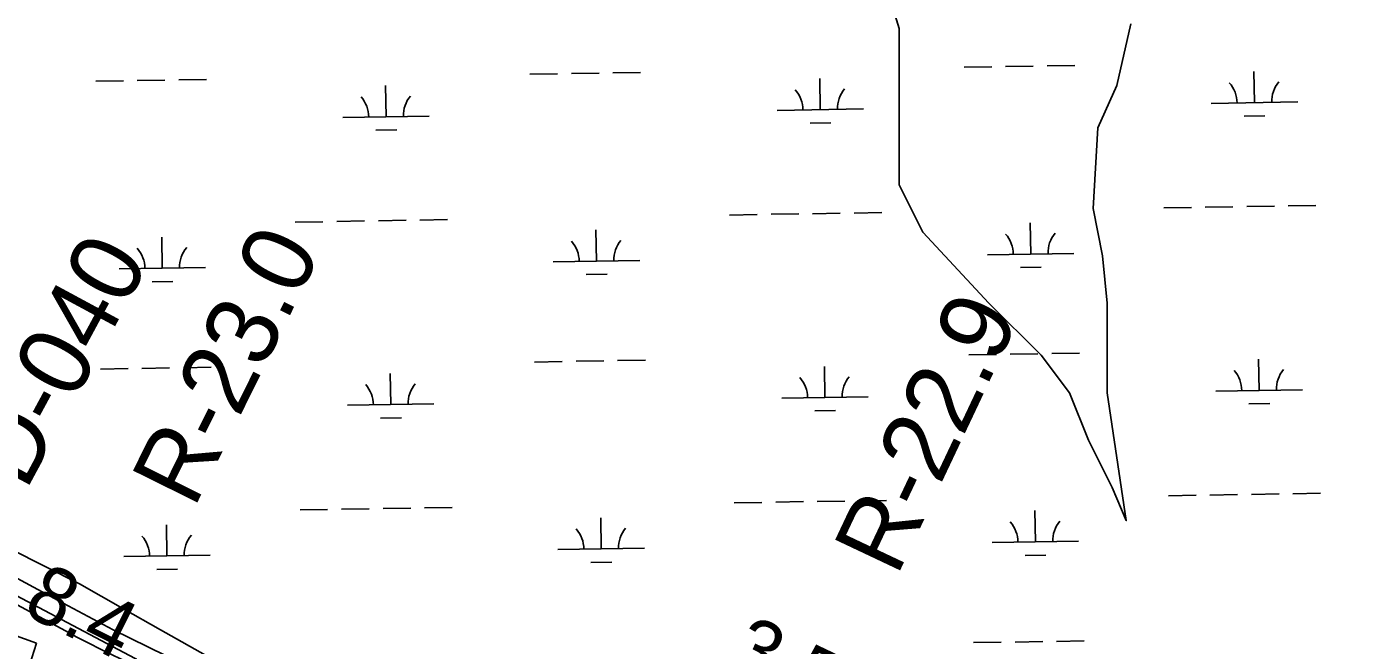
# Model space of a CAD drawing. Extents: x 3855477 to 3893699, y 299188 to 325115.
# Drawn here: x 3865905 to 3867459, y 315024 to 315738 of the extents above; entities that cross this region are included whole.
import ezdxf

# ---------------------------------------------------------------- set-up
doc = ezdxf.new("R2010")
doc.units = 0
for name, color, linetype in [('V-LEVE-TOET', 7, 'Continuous'), ('V-RIVR-EDGE', 7, 'Continuous'), ('V-RIVR-RANG', 7, 'Continuous'), ('V-RIVR-RANG-IDEN', 7, 'Continuous'), ('V-RRAP-FSHR', 7, 'Continuous'), ('V-RRAP-RVMT', 7, 'Continuous'), ('V-TOPO-MINR', 7, 'Continuous'), ('V-TOPO-SHOR', 7, 'Continuous'), ('V-WETL-SWMP', 7, 'Continuous')]:
    doc.layers.add(name, color=color, linetype=linetype)

msp = doc.modelspace()

# ---------------------------------------------------------------- linework, layer by layer
at = {"layer": 'V-LEVE-TOET'}
for points in [[(3866235.4, 314911.4), (3866259.2, 314902.4), (3866270.4, 314903.5), (3866272.4, 314911.4), (3866266.9, 314917.9), (3866245.6, 314933.2), (3866221.5, 314948.2), (3866197.3, 314962), (3866174.4, 314975.4), (3866153, 314987.1), (3866118.2, 315008.6), (3866060, 315041.4), (3866016.5, 315066.2), (3865966.2, 315094.5), (3865886.2, 315135.2)], [(3865851.4, 315124), (3865941.7, 315075.3), (3866005.1, 315041.6), (3866086.3, 315001.7), (3866168.6, 314955.9), (3866221.2, 314920.7), (3866235.4, 314911.4)]]:
    msp.add_lwpolyline(points, dxfattribs=at)
at = {"layer": 'V-RIVR-EDGE'}
msp.add_spline([(3862579.1, 316706.6), (3862618.9, 316682.6), (3862652.8, 316666.1), (3862683, 316656.5), (3862696.2, 316652.9), (3862701.3, 316646.9), (3862715.3, 316640.1), (3862730, 316634.5), (3862738.8, 316633.6), (3862748.3, 316626.1), (3862763.5, 316620.4), (3862771, 316614.8), (3862792.5, 316606), (3862806.8, 316598.8), (3862818, 316594.4), (3862834.3, 316586.8), (3862853, 316578.4), (3862861.8, 316570.8), (3862880.1, 316564.8), (3862890, 316564.7), (3862900, 316564.3), (3862907.6, 316561.5), (3862923.9, 316554.7), (3862944.6, 316544.7), (3862975.6, 316529), (3863008.7, 316511), (3863036.9, 316493.4), (3863051.3, 316484.2), (3863059.6, 316479.8), (3863073.1, 316469.4), (3863078.7, 316461.8), (3863091, 316455.4), (3863113.7, 316446.6), (3863137.2, 316440.6), (3863166.3, 316430.5), (3863183.4, 316425.7), (3863207.7, 316412.1), (3863228, 316399.7), (3863238.3, 316395.7), (3863252.7, 316390.5), (3863259.4, 316385.3), (3863266.6, 316378.1), (3863269.4, 316370.9), (3863279.3, 316363.3), (3863294.4, 316355.7), (3863309.2, 316346.9), (3863343, 316331.3), (3863355.3, 316322.1), (3863380.4, 316304.5), (3863423.4, 316277.3), (3863452, 316258.5), (3863472.7, 316247.6), (3863532.4, 316214.8), (3863576.2, 316192.8), (3863612, 316174), (3863663, 316147.9), (3863702, 316129.9), (3863762.1, 316101.5), (3863803.5, 316080.6), (3863847.7, 316056.6), (3863876.3, 316044.2), (3863896.6, 316031.8), (3863917.7, 316020.6), (3863971.8, 315991.3), (3864020.8, 315966.1), (3864054.2, 315946.5), (3864091.6, 315926.9), (3864114.7, 315913.7), (3864131.9, 315906.9), (3864147, 315897.7), (3864174, 315883.6), (3864183.2, 315874.1), (3864194.3, 315870.4), (3864207.5, 315866.8), (3864224.2, 315858.8), (3864239.3, 315850.4), (3864262.4, 315840), (3864273.6, 315837.2), (3864288.7, 315830.4), (3864303.8, 315827.9), (3864315.4, 315825.1), (3864338.5, 315817.1), (3864360.8, 315810.6), (3864391.4, 315792.2), (3864418.9, 315776.2), (3864436, 315762.2), (3864459, 315741.9), (3864510.4, 315709.8), (3864535.4, 315695.8), (3864549, 315685.4), (3864561.3, 315675.8), (3864568.8, 315666.7), (3864582.4, 315656.7), (3864595.1, 315647.1), (3864600.7, 315641.1), (3864607, 315633.1), (3864612.6, 315626.3), (3864620.2, 315622.7), (3864637.3, 315615.9), (3864659.6, 315609), (3864678.3, 315601), (3864697.4, 315595.4), (3864745.6, 315571.8), (3864769.9, 315563.7), (3864787.4, 315555.7), (3864811.2, 315540.5), (3864821.2, 315537.7), (3864833.2, 315537.7), (3864842.3, 315536.5), (3864849.5, 315531.3), (3864857.4, 315522.9), (3864872.2, 315516.9), (3864908, 315506), (3864925.1, 315500.4), (3864937.9, 315498.8), (3864948.6, 315491.6), (3864957, 315489.5), (3864964.2, 315487.5), (3865017.5, 315468.3), (3865068.5, 315449.8), (3865096.3, 315439.4), (3865128.6, 315425), (3865154.9, 315414.9), (3865176, 315401.7), (3865212.2, 315385.7), (3865243.6, 315368.5), (3865263.1, 315356.5), (3865277.9, 315348.1), (3865297, 315338.1), (3865316.5, 315331.2), (3865337.2, 315318), (3865369.4, 315298.4), (3865405.2, 315275.2), (3865431.9, 315259.6), (3865448.2, 315254), (3865473.7, 315238.4), (3865499.1, 315224.8), (3865515.1, 315218), (3865531.8, 315209.2), (3865549.7, 315199.5), (3865571.2, 315191.5), (3865609, 315173.1), (3865654, 315145.5), (3865693.8, 315123.1), (3865732.8, 315101.8), (3865776.9, 315077.4), (3865798.4, 315063.8), (3865826.7, 315046.6), (3865853.4, 315032.6), (3865883.2, 315017.4), (3865895.1, 315011.4), (3865904.3, 315003.8), (3865913, 314994.6), (3865919.8, 314990.2), (3865927.8, 314987.4), (3865939.7, 314983.4), (3865950.5, 314980.6), (3865961.6, 314976.5), (3865977.5, 314967.3), (3866028.9, 314942.9), (3866056.7, 314928.5), (3866076.6, 314915.3), (3866096.5, 314901.7), (3866120.4, 314888.5), (3866143.9, 314878.1), (3866161.4, 314867.2), (3866178.1, 314862.8), (3866201.2, 314856.8), (3866223.1, 314850.4), (3866245.8, 314837.5), (3866263.7, 314827.1), (3866282.8, 314818.7), (3866292.4, 314818.7), (3866300.8, 314818.3), (3866309.9, 314816.3), (3866326.7, 314808.7), (3866348.5, 314791.1), (3866360.1, 314786.3), (3866377.6, 314778.6), (3866387.5, 314775), (3866394.3, 314767.4), (3866401.9, 314762.2), (3866413.8, 314757), (3866423.4, 314751.4), (3866432.1, 314749.8), (3866437.7, 314746.2), (3866445.6, 314739.4), (3866454.4, 314732.2), (3866485.5, 314719), (3866510.5, 314708.6), (3866533.2, 314691.4), (3866542, 314691.3), (3866549.9, 314690.9), (3866556.3, 314686.5), (3866561.9, 314678.5), (3866573.8, 314670.1), (3866598.9, 314663.7), (3866631.1, 314649.3), (3866660.6, 314640.4), (3866694.9, 314628.4), (3866748.2, 314604.4), (3866780.4, 314591.5), (3866811.1, 314575.5), (3866846.9, 314561.5), (3866895.5, 314539), (3866932.1, 314524.6), (3866954.8, 314513.4), (3866988.3, 314500.5), (3867018.5, 314486.5), (3867041.2, 314475.3), (3867068.7, 314458.5), (3867097.3, 314440.1), (3867124, 314432.5), (3867147.1, 314433.2), (3867169.4, 314428), (3867197.3, 314417.1), (3867215.2, 314410.7), (3867238.7, 314401.5), (3867251.4, 314396.3), (3867258.6, 314395.9), (3867271.4, 314397.4), (3867288.1, 314397.8), (3867302.4, 314396.1), (3867345.5, 314385.3), (3867427.5, 314359.6), (3867438.3, 314357.9), (3867445, 314357.9), (3867453.4, 314369.5), (3867458.2, 314381.4), (3867462.3, 314395.8), (3867462.3, 314404.1), (3867460.7, 314411.7), (3867457.1, 314414.1), (3867450.8, 314416.1), (3867442.8, 314416.5), (3867438.8, 314420.1), (3867443.2, 314422.1), (3867451.6, 314428.1), (3867458.8, 314437.2), (3867459.6, 314442.8), (3867460, 314450.8), (3867463.6, 314455.1), (3867470.8, 314463.9), (3867472, 314469.5), (3867472.4, 314477), (3867471.6, 314485), (3867465.7, 314504.5), (3867463.7, 314514.5), (3867463.4, 314524.5), (3867464.2, 314541.2), (3867469.1, 314571.1), (3867474.7, 314579.8), (3867478.3, 314581.4), (3867485, 314582.6), (3867525.3, 314574.9), (3867536, 314568.9), (3867545.2, 314565.7), (3867555.1, 314566.5), (3867569.9, 314566.1), (3867581, 314559.7), (3867585, 314552.1), (3867591.7, 314543.7), (3867611.6, 314532.9), (3867628, 314518.1), (3867650.2, 314493.3), (3867659.8, 314484.9), (3867663.3, 314473), (3867663.3, 314455.4), (3867660.1, 314447.5), (3867647.3, 314446.3), (3867632.2, 314444.7), (3867612.6, 314438.4), (3867582.3, 314425.3)], degree=3, dxfattribs=at)
at = {"layer": 'V-RRAP-FSHR'}
msp.add_lwpolyline([(3866239.6, 314897.6), (3865860, 315098.5), (3865598.2, 315227.3), (3865158.2, 315473.7), (3864855.1, 315633.5), (3864567.4, 315789.9), (3864528.6, 315815.3), (3864457.8, 315882.7), (3864401.1, 315915.5), (3864176.2, 316007), (3864115.8, 316040.8), (3863978.3, 316124.1), (3863948.8, 316149.8), (3863903, 316175), (3863827.7, 316197.1), (3863791.6, 316214.7)], dxfattribs=at)
at = {"layer": 'V-RRAP-RVMT'}
for p, q in [((3865916.5, 315025.9), (3865781.5, 315075.3)), ((3865908.6, 315000.7), (3865916.5, 315025.9))]:
    msp.add_line(p, q, dxfattribs=at)
at = {"layer": 'V-TOPO-MINR'}
msp.add_lwpolyline([(3866240.1, 314907.1), (3866186.4, 314928.4), (3866133.4, 314951.4), (3866081, 314975.6), (3866004.1, 315012.5), (3865990.5, 315019.2), (3865976.9, 315026), (3865963.4, 315033), (3865950, 315040.1), (3865873.9, 315081.3)], dxfattribs=at)
at = {"layer": 'V-TOPO-SHOR'}
msp.add_lwpolyline([(3866897.2, 315791), (3866913.6, 315736.4), (3866913.6, 315605.1), (3866913.6, 315555.9), (3866941, 315501.2), (3867017.5, 315419.2), (3867077.7, 315359.1), (3867110.5, 315315.3), (3867132.4, 315260.6), (3867159.7, 315206), (3867176.1, 315167.7), (3867154.2, 315315.3), (3867154.2, 315364.5), (3867154.2, 315419.2), (3867148.8, 315473.9), (3867137.8, 315528.6), (3867143.3, 315621.5), (3867165.2, 315670.7), (3867181.6, 315741.8)], dxfattribs=at)
at = {"layer": 'V-WETL-SWMP'}
for p, q in [((3866988.7, 315691.8), (3867020.7, 315692.3)), ((3867036.7, 315692.6), (3867068.7, 315693.1)), ((3867084.7, 315693.4), (3867116.7, 315693.9)), ((3866033, 315676.3), (3866065, 315676.8)), ((3866081, 315677), (3866113, 315677.6)), ((3866486.9, 315683.6), (3866518.9, 315684.2)), ((3866534.9, 315684.4), (3866566.9, 315684.9)), ((3866582.9, 315685.2), (3866614.9, 315685.7)), ((3866822.4, 315642.7), (3866821.9, 315678.7)), ((3867324.3, 315650.9), (3867323.7, 315686.8)), ((3865985.1, 315675.5), (3866017, 315676)), ((3866320.6, 315634.5), (3866320, 315670.5)), ((3867274.3, 315650), (3867374.3, 315651.7)), ((3866270.6, 315633.7), (3866370.6, 315635.3)), ((3866772.5, 315641.9), (3866872.4, 315643.5)), ((3867312.5, 315635.2), (3867336.5, 315635.6)), ((3866308.9, 315618.9), (3866332.9, 315619.3)), ((3866810.7, 315627.1), (3866834.7, 315627.4)), ((3866717.6, 315520.9), (3866749.6, 315521.4)), ((3866765.6, 315521.7), (3866797.6, 315522.2)), ((3866813.6, 315522.4), (3866845.6, 315523)), ((3866861.6, 315523.2), (3866893.6, 315523.7)), ((3867219.4, 315529.1), (3867251.4, 315529.6)), ((3867267.4, 315529.8), (3867299.4, 315530.4)), ((3867315.4, 315530.6), (3867347.4, 315531.1)), ((3867363.4, 315531.4), (3867395.4, 315531.9)), ((3866215.7, 315512.7), (3866247.7, 315513.2)), ((3866263.7, 315513.5), (3866295.7, 315514)), ((3866311.7, 315514.3), (3866343.7, 315514.8)), ((3866359.7, 315515.1), (3866391.7, 315515.6)), ((3867065.7, 315475.8), (3867065.1, 315511.8)), ((3866062, 315459.5), (3866061.4, 315495.4)), ((3866563.8, 315467.6), (3866563.2, 315503.6)), ((3867015.7, 315475), (3867115.7, 315476.6)), ((3866012, 315458.6), (3866112, 315460.3)), ((3866513.8, 315466.8), (3866613.8, 315468.4)), ((3867053.9, 315460.2), (3867077.9, 315460.6)), ((3866050.2, 315443.8), (3866074.2, 315444.2)), ((3866552.1, 315452), (3866576.1, 315452.4)), ((3866492.3, 315351), (3866524.3, 315351.5)), ((3866540.3, 315351.8), (3866572.3, 315352.3)), ((3866588.3, 315352.6), (3866620.3, 315353.1)), ((3866994.2, 315359.2), (3867026.1, 315359.7)), ((3867042.1, 315360), (3867074.1, 315360.5)), ((3867090.1, 315360.8), (3867122.1, 315361.3)), ((3867329.7, 315318.2), (3867329.1, 315354.2)), ((3865990.5, 315342.8), (3866022.5, 315343.4)), ((3866038.5, 315343.6), (3866070.5, 315344.1)), ((3866086.5, 315344.4), (3866118.5, 315344.9)), ((3866326, 315301.9), (3866325.4, 315337.9)), ((3866827.9, 315310), (3866827.3, 315346)), ((3866777.9, 315309.2), (3866877.9, 315310.9)), ((3867279.7, 315317.4), (3867379.7, 315319)), ((3866276, 315301.1), (3866376, 315302.7)), ((3866816.1, 315294.4), (3866840.1, 315294.8)), ((3867318, 315302.6), (3867342, 315303)), ((3866314.3, 315286.2), (3866338.3, 315286.6)), ((3867224.8, 315196.4), (3867256.8, 315196.9)), ((3867272.8, 315197.2), (3867304.8, 315197.7)), ((3867320.8, 315198), (3867352.8, 315198.5)), ((3867368.8, 315198.8), (3867400.8, 315199.3)), ((3866221.2, 315180.1), (3866253.1, 315180.6)), ((3866269.1, 315180.9), (3866301.1, 315181.4)), ((3866317.1, 315181.6), (3866349.1, 315182.2)), ((3866365.1, 315182.4), (3866397.1, 315182.9)), ((3866723, 315188.3), (3866755, 315188.8)), ((3866771, 315189), (3866803, 315189.6)), ((3866819, 315189.8), (3866851, 315190.3)), ((3866867, 315190.6), (3866899, 315191.1)), ((3866569.2, 315135), (3866568.7, 315171)), ((3867071.1, 315143.2), (3867070.5, 315179.2)), ((3866067.4, 315126.8), (3866066.8, 315162.8)), ((3866519.3, 315134.2), (3866619.2, 315135.8)), ((3867021.1, 315142.4), (3867121.1, 315144)), ((3866017.4, 315126), (3866117.4, 315127.6)), ((3866557.5, 315119.4), (3866581.5, 315119.8)), ((3867059.3, 315127.5), (3867083.3, 315127.9)), ((3866055.7, 315111.2), (3866079.7, 315111.6)), ((3866999.6, 315026.6), (3867031.6, 315027.1)), ((3867047.6, 315027.3), (3867079.6, 315027.9)), ((3867095.6, 315028.1), (3867127.6, 315028.6))]:
    msp.add_line(p, q, dxfattribs=at)
for centre, start, end in [((3866767.2, 315642.3), 0.1615, 41.7052), ((3866877.7, 315644.1), 140.1615, 181.7052), ((3867269, 315650.4), 0.1615, 41.7052), ((3867379.5, 315652.2), 140.1615, 181.7052), ((3866265.4, 315634.1), 0.1615, 41.7052), ((3866375.8, 315635.9), 140.1615, 181.7052), ((3866508.6, 315467.2), 0.1615, 41.7052), ((3866619.1, 315469), 140.1615, 181.7052), ((3867010.4, 315475.4), 0.1615, 41.7052), ((3867120.9, 315477.2), 140.1615, 181.7052), ((3866006.7, 315459), 0.1615, 41.7052), ((3866117.2, 315460.8), 140.1615, 181.7052), ((3867274.5, 315317.8), 0.1615, 41.7052), ((3867384.9, 315319.6), 140.1615, 181.7052), ((3866270.8, 315301.4), 0.1615, 41.7052), ((3866381.3, 315303.2), 140.1615, 181.7052), ((3866772.6, 315309.6), 0.1615, 41.7052), ((3866883.1, 315311.4), 140.1615, 181.7052), ((3867015.8, 315142.7), 0.1615, 41.7052), ((3867126.3, 315144.5), 140.1615, 181.7052), ((3866012.2, 315126.4), 0.1615, 41.7052), ((3866122.6, 315128.2), 140.1615, 181.7052), ((3866514, 315134.6), 0.1615, 41.7052), ((3866624.5, 315136.4), 140.1615, 181.7052)]:
    msp.add_arc(centre, 35.2, start, end, dxfattribs=at)

# ---------------------------------------------------------------- texts
at = {"layer": 'V-RIVR-RANG'}
for s, rotation, p in [('8.4', 333.5383, (3865898.8, 315061)), ('3.5', 334.5683, (3866714.7, 314999.3))]:
    msp.add_text(s, height=67, rotation=rotation, dxfattribs=at).set_placement(p)
at = {"layer": 'V-RIVR-RANG-IDEN'}
for s, rotation, p in [('D-040', 61.6263, (3865904.2, 315201.1)), ('R-23.0', 63.6789, (3866098.5, 315180.5)), ('R-22.9', 64.7112, (3866910.9, 315101.9))]:
    msp.add_text(s, height=83, rotation=rotation, dxfattribs=at).set_placement(p)

doc.saveas('drawing.dxf')
